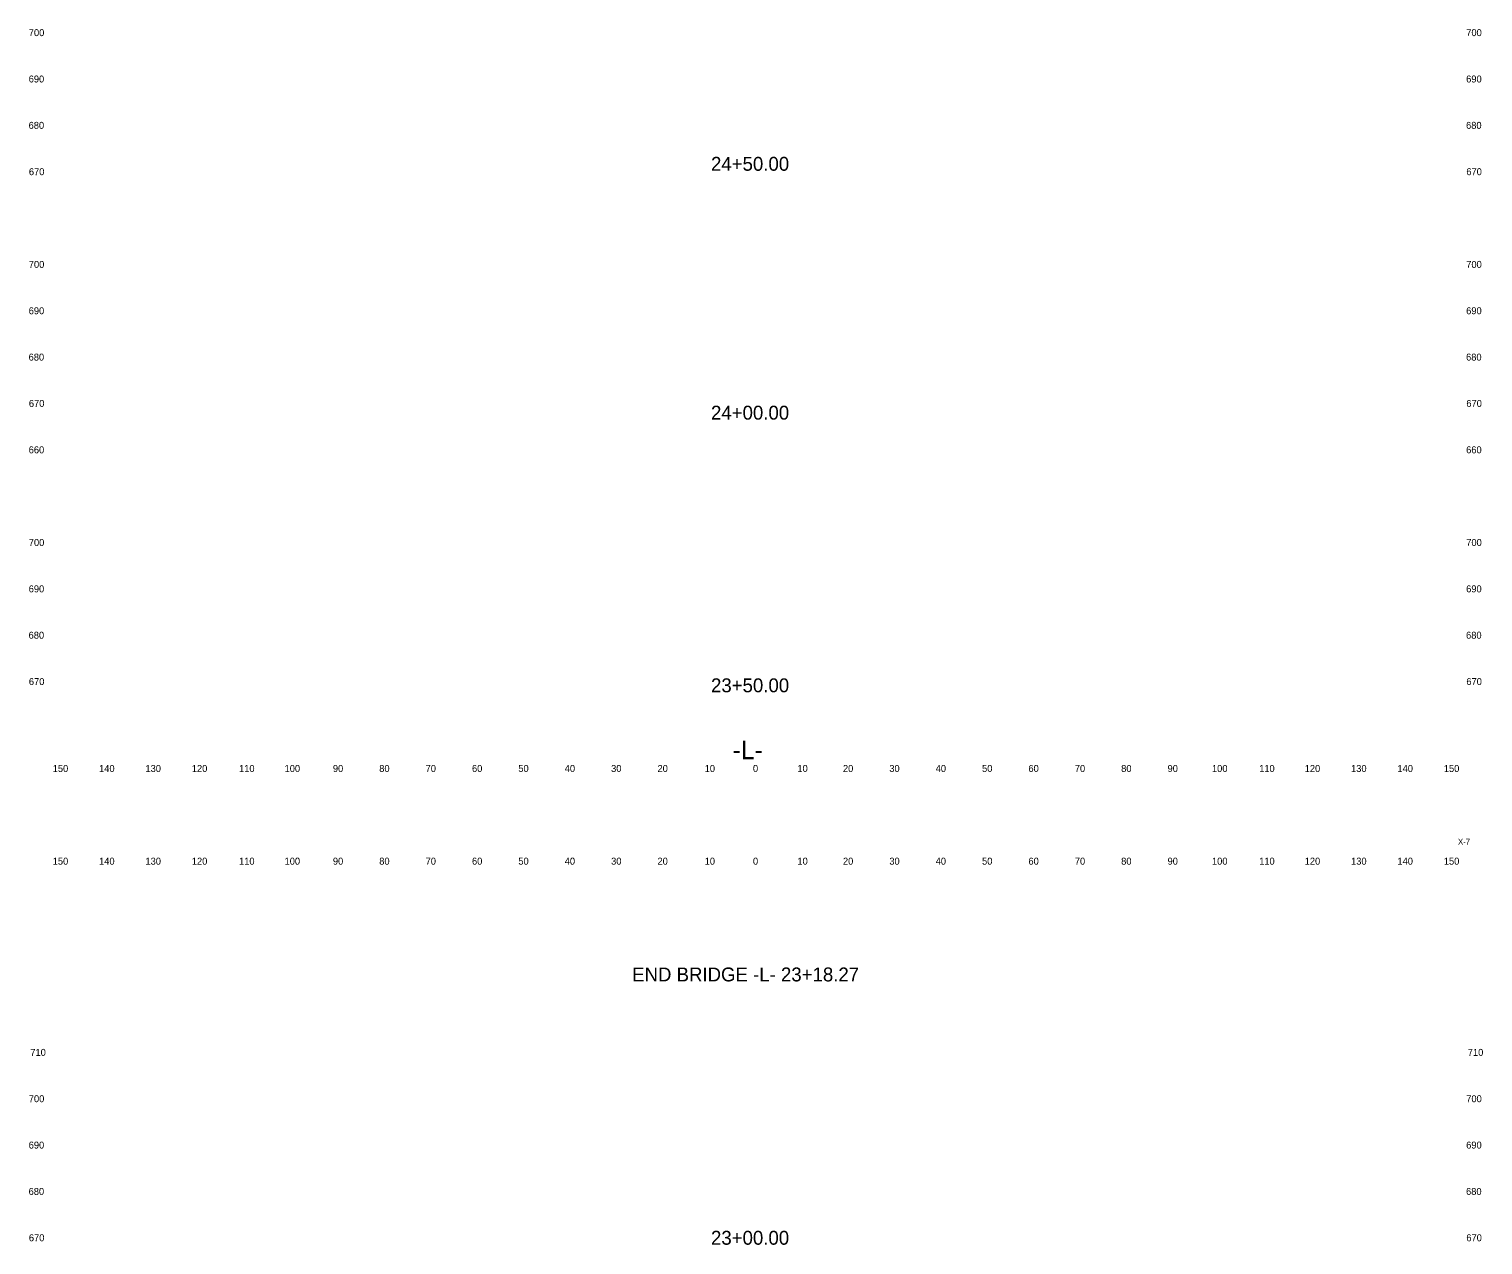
# Model space of a CAD drawing. Extents: x 3 to 317, y 0 to 2407.
# Drawn here: x 3.3 to 316.9, y 1219.2 to 1481.5 of the extents above; entities that cross this region are included whole.
import ezdxf

# ---------------------------------------------------------------- set-up
doc = ezdxf.new("R2010")
doc.units = 0
for name, color, linetype in [('Prop XS Ditch Standard Text', 7, 'Continuous'), ('Prop XS Dump Level', 7, 'Continuous'), ('Prop XS SE Text', 7, 'Continuous'), ('Prop XS Sheet Number', 7, 'Continuous'), ('Prop XS SS Elevation Text', 7, 'Continuous')]:
    doc.layers.add(name, color=color, linetype=linetype)

msp = doc.modelspace()

# ---------------------------------------------------------------- texts
at = {"layer": 'Prop XS Ditch Standard Text'}
for s, p in [('24+50.00', (150.41, 1450.95)), ('24+00.00', (150.41, 1397.26)), ('23+50.00', (150.41, 1338.44)), ('END BRIDGE -L- 23+18.27', (133.4, 1276.06)), ('23+00.00', (150.41, 1219.25))]:
    msp.add_text(s, height=3, dxfattribs=at).set_placement(p)
at = {"layer": 'Prop XS Dump Level'}
for s, p in [('150', (8.44, 1321.25)), ('140', (18.44, 1321.25)), ('130', (28.44, 1321.25)), ('120', (38.44, 1321.25)), ('110', (48.62, 1321.25)), ('100', (58.44, 1321.25)), ('90', (68.86, 1321.25)), ('80', (78.86, 1321.25)), ('70', (88.86, 1321.25)), ('60', (98.86, 1321.25)), ('50', (108.86, 1321.25)), ('40', (118.86, 1321.25)), ('30', (128.86, 1321.25)), ('20', (138.86, 1321.25)), ('10', (149.04, 1321.25)), ('0', (159.45, 1321.25)), ('10', (169.04, 1321.25)), ('20', (178.86, 1321.25)), ('30', (188.86, 1321.25)), ('40', (198.86, 1321.25)), ('50', (208.86, 1321.25)), ('60', (218.86, 1321.25)), ('70', (228.86, 1321.25)), ('80', (238.86, 1321.25)), ('90', (248.86, 1321.25)), ('100', (258.44, 1321.25)), ('110', (268.62, 1321.25)), ('120', (278.44, 1321.25)), ('130', (288.44, 1321.25)), ('140', (298.44, 1321.25)), ('150', (308.44, 1321.25)), ('150', (8.44, 1301.25)), ('140', (18.44, 1301.25)), ('130', (28.44, 1301.25)), ('120', (38.44, 1301.25)), ('110', (48.62, 1301.25)), ('100', (58.44, 1301.25)), ('90', (68.86, 1301.25)), ('80', (78.86, 1301.25)), ('70', (88.86, 1301.25)), ('60', (98.86, 1301.25)), ('50', (108.86, 1301.25)), ('40', (118.86, 1301.25)), ('30', (128.86, 1301.25)), ('20', (138.86, 1301.25)), ('10', (149.04, 1301.25)), ('0', (159.45, 1301.25)), ('10', (169.04, 1301.25)), ('20', (178.86, 1301.25)), ('30', (188.86, 1301.25)), ('40', (198.86, 1301.25)), ('50', (208.86, 1301.25)), ('60', (218.86, 1301.25)), ('70', (228.86, 1301.25)), ('80', (238.86, 1301.25)), ('90', (248.86, 1301.25)), ('100', (258.44, 1301.25)), ('110', (268.62, 1301.25)), ('120', (278.44, 1301.25)), ('130', (288.44, 1301.25)), ('140', (298.44, 1301.25)), ('150', (308.44, 1301.25))]:
    msp.add_text(s, height=1.5, dxfattribs=at).set_placement(p)
at = {"layer": 'Prop XS SE Text'}
for s, p in [('700', (3.28, 1480)), ('700', (313.28, 1480)), ('690', (3.26, 1470)), ('690', (313.26, 1470)), ('680', (3.24, 1460)), ('680', (313.24, 1460)), ('670', (3.3, 1450)), ('670', (313.3, 1450)), ('700', (3.28, 1430)), ('700', (313.28, 1430)), ('690', (3.26, 1420)), ('690', (313.26, 1420)), ('680', (3.24, 1410)), ('680', (313.24, 1410)), ('670', (3.3, 1400)), ('670', (313.3, 1400)), ('660', (3.26, 1390)), ('660', (313.26, 1390)), ('700', (3.28, 1370)), ('700', (313.28, 1370)), ('690', (3.26, 1360)), ('690', (313.26, 1360)), ('680', (3.24, 1350)), ('680', (313.24, 1350)), ('670', (3.3, 1340)), ('670', (313.3, 1340)), ('710', (3.61, 1260)), ('710', (313.61, 1260)), ('700', (3.28, 1250)), ('700', (313.28, 1250)), ('690', (3.26, 1240)), ('690', (313.26, 1240)), ('680', (3.24, 1230)), ('680', (313.24, 1230)), ('670', (3.3, 1220)), ('670', (313.3, 1220))]:
    msp.add_text(s, height=1.5, dxfattribs=at).set_placement(p)
at = {"layer": 'Prop XS Sheet Number'}
msp.add_text('X-7', height=1.25, dxfattribs=at).set_placement((311.5, 1305.58))
at = {"layer": 'Prop XS SS Elevation Text'}
msp.add_text('-L-', height=4, dxfattribs=at).set_placement((155.06, 1324))

doc.saveas('drawing.dxf')
